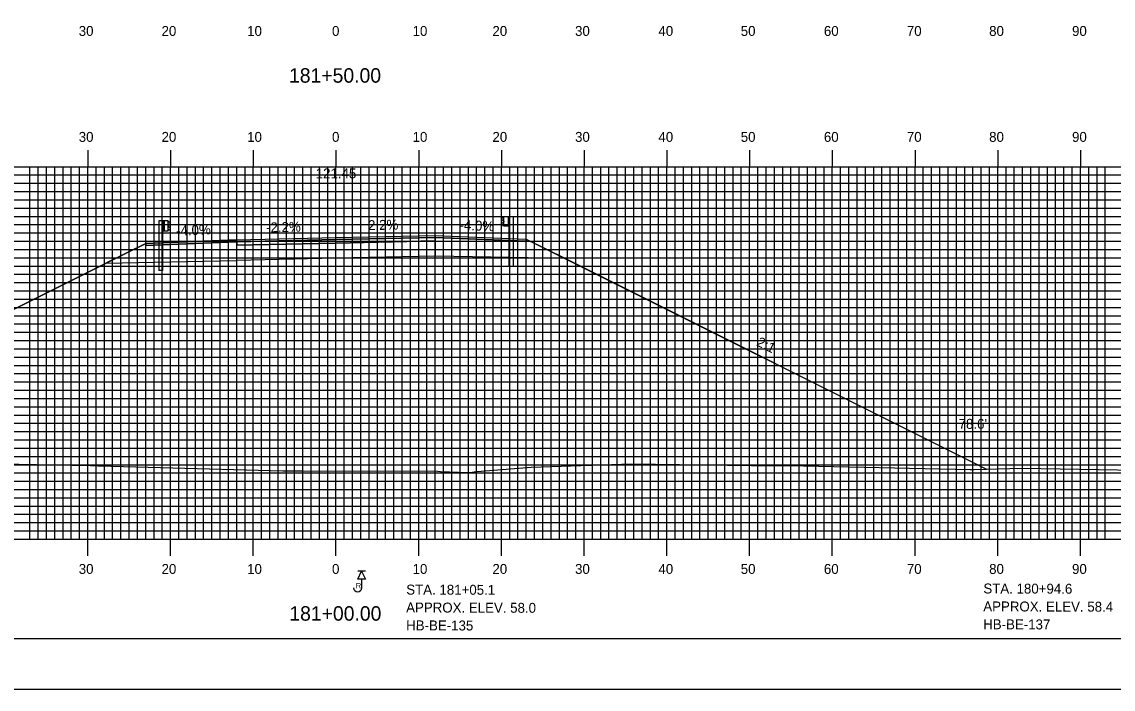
# Model space of a CAD drawing. Extents: x 1786189 to 1786532, y 442591 to 442811.
# Drawn here: x 1786316.6 to 1786448.5, y 442590.5 to 442671.2 of the extents above; entities that cross this region are included whole.
import ezdxf

# ---------------------------------------------------------------- set-up
doc = ezdxf.new("R2010")
doc.units = 0
for name, color, linetype in [('ANNOTATION', 7, 'Continuous'), ('BORDER', 7, 'Continuous'), ('BORING - NO REFUSAL', 7, 'Continuous'), ('BORING - REFUSAL', 7, 'Continuous'), ('D_Guardrail_Beam_Lt', 7, 'Continuous'), ('D_Guardrail_Beam_Rt', 7, 'Continuous'), ('D_Roadway_Centerline', 7, 'Continuous'), ('D_Roadway_Centerline_Text', 7, 'Continuous'), ('D_Roadway_Edge_Shoulder', 7, 'Continuous'), ('D_Roadway_Edge_TW', 7, 'Continuous'), ('D_Roadway_Pavement', 7, 'Continuous'), ('D_Roadway_SlopeLines', 7, 'Continuous'), ('D_Roadway_SubGrade', 7, 'Continuous'), ('D_Text_Standard', 7, 'Continuous'), ('H_V ANNOTATION', 7, 'Continuous'), ('MAJOR', 7, 'Continuous'), ('MINOR', 7, 'Continuous'), ('PLOT BOUNDARY', 7, 'Continuous'), ('S_Roadway_Centerline', 7, 'Continuous')]:
    doc.layers.add(name, color=color, linetype=linetype)

msp = doc.modelspace()

# ---------------------------------------------------------------- linework, layer by layer
at = {"layer": 'BORDER'}
msp.add_lwpolyline([(1786204.96, 442596.67), (1786524.96, 442596.67), (1786524.96, 442806.67), (1786204.96, 442806.67)], close=True, dxfattribs=at)
at = {"layer": 'BORING - NO REFUSAL'}
for p, q in [((1786358.14, 442604.81), (1786357.19, 442604.81)), ((1786357.66, 442603.85), (1786357.66, 442602.79))]:
    msp.add_line(p, q, dxfattribs=at)
msp.add_lwpolyline([(1786357.66, 442604.81), (1786358.14, 442603.85), (1786357.19, 442603.85)], close=True, dxfattribs=at)
msp.add_arc((1786357.18, 442602.79), 0.485, 180, 0, dxfattribs=at)
at = {"layer": 'D_Guardrail_Beam_Lt'}
for p, q in [((1786333.14, 442647.11), (1786333.14, 442641.11)), ((1786333.61, 442647.11), (1786333.14, 442647.11)), ((1786334.29, 442647.11), (1786333.61, 442647.11)), ((1786333.61, 442647.11), (1786333.61, 442645.94)), ((1786333.67, 442647.11), (1786333.67, 442645.94)), ((1786333.77, 442647.11), (1786333.77, 442645.94)), ((1786334.29, 442645.94), (1786334.29, 442647.11)), ((1786334.29, 442647.03), (1786334.37, 442647.01)), ((1786334.53, 442646.76), (1786334.33, 442646.63)), ((1786334.38, 442647.01), (1786334.53, 442646.91)), ((1786333.61, 442645.94), (1786334.29, 442645.94)), ((1786333.63, 442641.11), (1786333.63, 442645.94)), ((1786334.37, 442646.04), (1786334.29, 442646.03)), ((1786334.3, 442646.56), (1786334.3, 442646.49)), ((1786334.33, 442646.43), (1786334.53, 442646.29)), ((1786334.53, 442646.15), (1786334.38, 442646.05)), ((1786333.63, 442641.11), (1786333.14, 442641.11))]:
    msp.add_line(p, q, dxfattribs=at)
for centre, major_axis, start_param, end_param in [((1786334.36, 442646.97), (0.0417, 0), 0.959931, 1.376053), ((1786334.48, 442646.83), (0.0877, 0), 5.323254, 7.243116), ((1786334.38, 442646.56), (-0.0789, 0), 5.323254, 6.283185), ((1786334.38, 442646.49), (-0.0789, 0), 6.283185, 7.243116), ((1786334.36, 442646.08), (0.0417, 0), 4.907132, 5.323254), ((1786334.48, 442646.22), (0.0877, 0), 5.323254, 7.243116)]:
    msp.add_ellipse(centre, major_axis=major_axis, ratio=0.995501, start_param=start_param, end_param=end_param, dxfattribs=at)
at = {"layer": 'D_Guardrail_Beam_Rt'}
for p, q in [((1786374.75, 442647.53), (1786374.6, 442647.43)), ((1786374.6, 442647.29), (1786374.8, 442647.15)), ((1786374.8, 442646.95), (1786374.6, 442646.82)), ((1786374.84, 442647.55), (1786374.76, 442647.54)), ((1786374.83, 442647.09), (1786374.83, 442647.02)), ((1786374.84, 442647.64), (1786375.52, 442647.64)), ((1786374.84, 442646.47), (1786374.84, 442647.64)), ((1786375.36, 442647.64), (1786375.36, 442646.47)), ((1786375.46, 442647.64), (1786375.46, 442646.47)), ((1786375.52, 442647.64), (1786375.99, 442647.64)), ((1786375.52, 442647.64), (1786375.52, 442646.47)), ((1786375.99, 442647.64), (1786375.99, 442641.64)), ((1786374.6, 442646.68), (1786374.75, 442646.58)), ((1786374.76, 442646.57), (1786374.84, 442646.55)), ((1786375.52, 442646.47), (1786374.84, 442646.47)), ((1786375.5, 442641.64), (1786375.5, 442646.47)), ((1786375.5, 442641.64), (1786375.99, 442641.64))]:
    msp.add_line(p, q, dxfattribs=at)
for centre, major_axis, start_param, end_param in [((1786374.65, 442647.36), (-0.0877, 0), 5.323254, 7.243116), ((1786374.65, 442646.75), (-0.0877, 0), 5.323254, 7.243116), ((1786374.77, 442647.5), (-0.0417, 0), 4.907132, 5.323254), ((1786374.75, 442647.09), (0.0789, 0), 0, 0.959931), ((1786374.75, 442647.02), (0.0789, 0), 5.323254, 6.283185), ((1786374.77, 442646.61), (-0.0417, 0), 0.959931, 1.376053)]:
    msp.add_ellipse(centre, major_axis=major_axis, ratio=0.995501, start_param=start_param, end_param=end_param, dxfattribs=at)
at = {"layer": 'D_Roadway_Centerline'}
msp.add_lwpolyline([(1786279.32, 442618.29), (1786326.75, 442642), (1786331.56, 442644.41), (1786334.56, 442644.53), (1786342.56, 442644.85), (1786354.56, 442645.11), (1786366.56, 442645.37), (1786374.56, 442645.05), (1786377.56, 442644.93), (1786382.31, 442642.56), (1786433.18, 442617.13)], dxfattribs=at)
at = {"layer": 'D_Roadway_Edge_Shoulder'}
for points in [[(1786342.56, 442644.85), (1786334.56, 442644.53), (1786334.56, 442644.53), (1786331.56, 442644.41), (1786331.56, 442644.16), (1786342.56, 442644.6)], [(1786366.56, 442645.37), (1786374.56, 442645.05), (1786374.56, 442645.05), (1786377.56, 442644.93), (1786377.56, 442644.68), (1786366.56, 442645.12)]]:
    msp.add_lwpolyline(points, close=True, dxfattribs=at)
at = {"layer": 'D_Roadway_Edge_TW'}
msp.add_lwpolyline([(1786342.56, 442644.6), (1786342.56, 442644.85), (1786354.56, 442645.11), (1786366.56, 442645.37), (1786366.56, 442645.12), (1786354.56, 442644.86)], close=True, dxfattribs=at)
at = {"layer": 'D_Roadway_Pavement'}
msp.add_lwpolyline([(1786342.56, 442644.18), (1786342.56, 442644.6), (1786354.56, 442644.86), (1786366.56, 442645.12), (1786366.56, 442644.71), (1786354.56, 442644.44)], close=True, dxfattribs=at)
for points in [[(1786342.56, 442644.6), (1786342.56, 442644.18)], [(1786366.56, 442645.12), (1786366.56, 442644.71)]]:
    msp.add_lwpolyline(points, dxfattribs=at)
at = {"layer": 'D_Roadway_SlopeLines'}
for points in [[(1786331.56, 442644.41), (1786279.32, 442618.29)], [(1786377.56, 442644.93), (1786433.18, 442617.13)]]:
    msp.add_lwpolyline(points, dxfattribs=at)
at = {"layer": 'D_Roadway_SubGrade'}
for points in [[(1786342.56, 442644.18), (1786342.56, 442644.6), (1786331.56, 442644.16), (1786331.56, 442644.41), (1786326.75, 442642), (1786342.56, 442642.35)], [(1786342.56, 442642.35), (1786342.56, 442644.6), (1786342.56, 442644.18), (1786354.56, 442644.44), (1786366.56, 442644.71), (1786366.56, 442645.12), (1786366.56, 442642.87), (1786354.56, 442642.61)], [(1786366.56, 442644.71), (1786366.56, 442645.12), (1786377.56, 442644.68), (1786377.56, 442644.93), (1786382.31, 442642.56), (1786366.56, 442642.87)]]:
    msp.add_lwpolyline(points, close=True, dxfattribs=at)
at = {"layer": 'MAJOR'}
for p, q in [((1786324.56, 442655.67), (1786324.56, 442653.67)), ((1786334.56, 442655.67), (1786334.56, 442653.67)), ((1786344.56, 442655.67), (1786344.56, 442653.67)), ((1786354.56, 442655.67), (1786354.56, 442653.67)), ((1786364.56, 442655.67), (1786364.56, 442653.67)), ((1786374.56, 442655.67), (1786374.56, 442653.67)), ((1786384.56, 442655.67), (1786384.56, 442653.67)), ((1786394.56, 442655.67), (1786394.56, 442653.67)), ((1786404.56, 442655.67), (1786404.56, 442653.67)), ((1786414.56, 442655.67), (1786414.56, 442653.67)), ((1786424.56, 442655.67), (1786424.56, 442653.67)), ((1786434.56, 442655.67), (1786434.56, 442653.67)), ((1786444.56, 442655.67), (1786444.56, 442653.67)), ((1786214.56, 442653.67), (1786494.56, 442653.67)), ((1786214.56, 442653.67), (1786494.56, 442653.67)), ((1786324.56, 442608.67), (1786324.56, 442653.67)), ((1786334.56, 442608.67), (1786334.56, 442653.67)), ((1786344.56, 442608.67), (1786344.56, 442653.67)), ((1786354.56, 442608.67), (1786354.56, 442653.67)), ((1786364.56, 442608.67), (1786364.56, 442653.67)), ((1786374.56, 442608.67), (1786374.56, 442653.67)), ((1786384.56, 442608.67), (1786384.56, 442653.67)), ((1786394.56, 442608.67), (1786394.56, 442653.67)), ((1786404.56, 442608.67), (1786404.56, 442653.67)), ((1786414.56, 442608.67), (1786414.56, 442653.67)), ((1786424.56, 442608.67), (1786424.56, 442653.67)), ((1786434.56, 442608.67), (1786434.56, 442653.67)), ((1786444.56, 442608.67), (1786444.56, 442653.67)), ((1786214.56, 442648.67), (1786494.56, 442648.67)), ((1786214.56, 442643.67), (1786494.56, 442643.67)), ((1786214.56, 442638.67), (1786494.56, 442638.67)), ((1786214.56, 442633.67), (1786494.56, 442633.67)), ((1786214.56, 442628.67), (1786494.56, 442628.67)), ((1786214.56, 442623.67), (1786494.56, 442623.67)), ((1786214.56, 442618.67), (1786494.56, 442618.67)), ((1786214.56, 442613.67), (1786494.56, 442613.67)), ((1786214.56, 442608.67), (1786494.56, 442608.67)), ((1786214.56, 442608.67), (1786494.56, 442608.67)), ((1786324.56, 442606.66), (1786324.56, 442608.67)), ((1786334.56, 442606.66), (1786334.56, 442608.67)), ((1786344.56, 442606.66), (1786344.56, 442608.67)), ((1786354.56, 442606.66), (1786354.56, 442608.67)), ((1786364.56, 442606.66), (1786364.56, 442608.67)), ((1786374.56, 442606.66), (1786374.56, 442608.67)), ((1786384.56, 442606.66), (1786384.56, 442608.67)), ((1786394.56, 442606.66), (1786394.56, 442608.67)), ((1786404.56, 442606.66), (1786404.56, 442608.67)), ((1786414.56, 442606.66), (1786414.56, 442608.67)), ((1786424.56, 442606.66), (1786424.56, 442608.67)), ((1786434.56, 442606.66), (1786434.56, 442608.67)), ((1786444.56, 442606.66), (1786444.56, 442608.67))]:
    msp.add_line(p, q, dxfattribs=at)
at = {"layer": 'MINOR'}
for p, q in [((1786317.56, 442608.67), (1786317.56, 442653.67)), ((1786318.56, 442608.67), (1786318.56, 442653.67)), ((1786319.56, 442608.67), (1786319.56, 442653.67)), ((1786320.56, 442608.67), (1786320.56, 442653.67)), ((1786321.56, 442608.67), (1786321.56, 442653.67)), ((1786322.56, 442608.67), (1786322.56, 442653.67)), ((1786323.56, 442608.67), (1786323.56, 442653.67)), ((1786325.56, 442608.67), (1786325.56, 442653.67)), ((1786326.56, 442608.67), (1786326.56, 442653.67)), ((1786327.56, 442608.67), (1786327.56, 442653.67)), ((1786328.56, 442608.67), (1786328.56, 442653.67)), ((1786329.56, 442608.67), (1786329.56, 442653.67)), ((1786330.56, 442608.67), (1786330.56, 442653.67)), ((1786331.56, 442608.67), (1786331.56, 442653.67)), ((1786332.56, 442608.67), (1786332.56, 442653.67)), ((1786333.56, 442608.67), (1786333.56, 442653.67)), ((1786335.56, 442608.67), (1786335.56, 442653.67)), ((1786336.56, 442608.67), (1786336.56, 442653.67)), ((1786337.56, 442608.67), (1786337.56, 442653.67)), ((1786338.56, 442608.67), (1786338.56, 442653.67)), ((1786339.56, 442608.67), (1786339.56, 442653.67)), ((1786340.56, 442608.67), (1786340.56, 442653.67)), ((1786341.56, 442608.67), (1786341.56, 442653.67)), ((1786342.56, 442608.67), (1786342.56, 442653.67)), ((1786343.56, 442608.67), (1786343.56, 442653.67)), ((1786345.56, 442608.67), (1786345.56, 442653.67)), ((1786346.56, 442608.67), (1786346.56, 442653.67)), ((1786347.56, 442608.67), (1786347.56, 442653.67)), ((1786348.56, 442608.67), (1786348.56, 442653.67)), ((1786349.56, 442608.67), (1786349.56, 442653.67)), ((1786350.56, 442608.67), (1786350.56, 442653.67)), ((1786351.56, 442608.67), (1786351.56, 442653.67)), ((1786352.56, 442608.67), (1786352.56, 442653.67)), ((1786353.56, 442608.67), (1786353.56, 442653.67)), ((1786355.56, 442608.67), (1786355.56, 442653.67)), ((1786356.56, 442608.67), (1786356.56, 442653.67)), ((1786357.56, 442608.67), (1786357.56, 442653.67)), ((1786358.56, 442608.67), (1786358.56, 442653.67)), ((1786359.56, 442608.67), (1786359.56, 442653.67)), ((1786360.56, 442608.67), (1786360.56, 442653.67)), ((1786361.56, 442608.67), (1786361.56, 442653.67)), ((1786362.56, 442608.67), (1786362.56, 442653.67)), ((1786363.56, 442608.67), (1786363.56, 442653.67)), ((1786365.56, 442608.67), (1786365.56, 442653.67)), ((1786366.56, 442608.67), (1786366.56, 442653.67)), ((1786367.56, 442608.67), (1786367.56, 442653.67)), ((1786368.56, 442608.67), (1786368.56, 442653.67)), ((1786369.56, 442608.67), (1786369.56, 442653.67)), ((1786370.56, 442608.67), (1786370.56, 442653.67)), ((1786371.56, 442608.67), (1786371.56, 442653.67)), ((1786372.56, 442608.67), (1786372.56, 442653.67)), ((1786373.56, 442608.67), (1786373.56, 442653.67)), ((1786375.56, 442608.67), (1786375.56, 442653.67)), ((1786376.56, 442608.67), (1786376.56, 442653.67)), ((1786377.56, 442608.67), (1786377.56, 442653.67)), ((1786378.56, 442608.67), (1786378.56, 442653.67)), ((1786379.56, 442608.67), (1786379.56, 442653.67)), ((1786380.56, 442608.67), (1786380.56, 442653.67)), ((1786381.56, 442608.67), (1786381.56, 442653.67)), ((1786382.56, 442608.67), (1786382.56, 442653.67)), ((1786383.56, 442608.67), (1786383.56, 442653.67)), ((1786385.56, 442608.67), (1786385.56, 442653.67)), ((1786386.56, 442608.67), (1786386.56, 442653.67)), ((1786387.56, 442608.67), (1786387.56, 442653.67)), ((1786388.56, 442608.67), (1786388.56, 442653.67)), ((1786389.56, 442608.67), (1786389.56, 442653.67)), ((1786390.56, 442608.67), (1786390.56, 442653.67)), ((1786391.56, 442608.67), (1786391.56, 442653.67)), ((1786392.56, 442608.67), (1786392.56, 442653.67)), ((1786393.56, 442608.67), (1786393.56, 442653.67)), ((1786395.56, 442608.67), (1786395.56, 442653.67)), ((1786396.56, 442608.67), (1786396.56, 442653.67)), ((1786397.56, 442608.67), (1786397.56, 442653.67)), ((1786398.56, 442608.67), (1786398.56, 442653.67)), ((1786399.56, 442608.67), (1786399.56, 442653.67)), ((1786400.56, 442608.67), (1786400.56, 442653.67)), ((1786401.56, 442608.67), (1786401.56, 442653.67)), ((1786402.56, 442608.67), (1786402.56, 442653.67)), ((1786403.56, 442608.67), (1786403.56, 442653.67)), ((1786405.56, 442608.67), (1786405.56, 442653.67)), ((1786406.56, 442608.67), (1786406.56, 442653.67)), ((1786407.56, 442608.67), (1786407.56, 442653.67)), ((1786408.56, 442608.67), (1786408.56, 442653.67)), ((1786409.56, 442608.67), (1786409.56, 442653.67)), ((1786410.56, 442608.67), (1786410.56, 442653.67)), ((1786411.56, 442608.67), (1786411.56, 442653.67)), ((1786412.56, 442608.67), (1786412.56, 442653.67)), ((1786413.56, 442608.67), (1786413.56, 442653.67)), ((1786415.56, 442608.67), (1786415.56, 442653.67)), ((1786416.56, 442608.67), (1786416.56, 442653.67)), ((1786417.56, 442608.67), (1786417.56, 442653.67)), ((1786418.56, 442608.67), (1786418.56, 442653.67)), ((1786419.56, 442608.67), (1786419.56, 442653.67)), ((1786420.56, 442608.67), (1786420.56, 442653.67)), ((1786421.56, 442608.67), (1786421.56, 442653.67)), ((1786422.56, 442608.67), (1786422.56, 442653.67)), ((1786423.56, 442608.67), (1786423.56, 442653.67)), ((1786425.56, 442608.67), (1786425.56, 442653.67)), ((1786426.56, 442608.67), (1786426.56, 442653.67)), ((1786427.56, 442608.67), (1786427.56, 442653.67)), ((1786428.56, 442608.67), (1786428.56, 442653.67)), ((1786429.56, 442608.67), (1786429.56, 442653.67)), ((1786430.56, 442608.67), (1786430.56, 442653.67)), ((1786431.56, 442608.67), (1786431.56, 442653.67)), ((1786432.56, 442608.67), (1786432.56, 442653.67)), ((1786433.56, 442608.67), (1786433.56, 442653.67)), ((1786435.56, 442608.67), (1786435.56, 442653.67)), ((1786436.56, 442608.67), (1786436.56, 442653.67)), ((1786437.56, 442608.67), (1786437.56, 442653.67)), ((1786438.56, 442608.67), (1786438.56, 442653.67)), ((1786439.56, 442608.67), (1786439.56, 442653.67)), ((1786440.56, 442608.67), (1786440.56, 442653.67)), ((1786441.56, 442608.67), (1786441.56, 442653.67)), ((1786442.56, 442608.67), (1786442.56, 442653.67)), ((1786443.56, 442608.67), (1786443.56, 442653.67)), ((1786445.56, 442608.67), (1786445.56, 442653.67)), ((1786446.56, 442608.67), (1786446.56, 442653.67)), ((1786447.56, 442608.67), (1786447.56, 442653.67)), ((1786214.56, 442652.67), (1786494.56, 442652.67)), ((1786214.56, 442651.67), (1786494.56, 442651.67)), ((1786214.56, 442650.67), (1786494.56, 442650.67)), ((1786214.56, 442649.67), (1786494.56, 442649.67)), ((1786214.56, 442647.67), (1786494.56, 442647.67)), ((1786214.56, 442646.67), (1786494.56, 442646.67)), ((1786214.56, 442645.67), (1786494.56, 442645.67)), ((1786214.56, 442644.67), (1786494.56, 442644.67)), ((1786214.56, 442642.67), (1786494.56, 442642.67)), ((1786214.56, 442641.67), (1786494.56, 442641.67)), ((1786214.56, 442640.67), (1786494.56, 442640.67)), ((1786214.56, 442639.67), (1786494.56, 442639.67)), ((1786214.56, 442637.67), (1786494.56, 442637.67)), ((1786214.56, 442636.67), (1786494.56, 442636.67)), ((1786214.56, 442635.67), (1786494.56, 442635.67)), ((1786214.56, 442634.67), (1786494.56, 442634.67)), ((1786214.56, 442632.67), (1786494.56, 442632.67)), ((1786214.56, 442631.67), (1786494.56, 442631.67)), ((1786214.56, 442630.67), (1786494.56, 442630.67)), ((1786214.56, 442629.67), (1786494.56, 442629.67)), ((1786214.56, 442627.67), (1786494.56, 442627.67)), ((1786214.56, 442626.67), (1786494.56, 442626.67)), ((1786214.56, 442625.67), (1786494.56, 442625.67)), ((1786214.56, 442624.67), (1786494.56, 442624.67)), ((1786214.56, 442622.67), (1786494.56, 442622.67)), ((1786214.56, 442621.67), (1786494.56, 442621.67)), ((1786214.56, 442620.67), (1786494.56, 442620.67)), ((1786214.56, 442619.67), (1786494.56, 442619.67)), ((1786214.56, 442617.67), (1786494.56, 442617.67)), ((1786214.56, 442616.67), (1786494.56, 442616.67)), ((1786214.56, 442615.67), (1786494.56, 442615.67)), ((1786214.56, 442614.67), (1786494.56, 442614.67)), ((1786214.56, 442612.67), (1786494.56, 442612.67)), ((1786214.56, 442611.67), (1786494.56, 442611.67)), ((1786214.56, 442610.67), (1786494.56, 442610.67)), ((1786214.56, 442609.67), (1786494.56, 442609.67))]:
    msp.add_line(p, q, dxfattribs=at)
at = {"layer": 'PLOT BOUNDARY'}
msp.add_lwpolyline([(1786188.78, 442590.55), (1786528.78, 442590.55), (1786528.78, 442810.55), (1786188.78, 442810.55)], close=True, dxfattribs=at)
at = {"layer": 'S_Roadway_Centerline'}
msp.add_lwpolyline([(1786314.04, 442617.77), (1786324.86, 442617.57), (1786325.3, 442617.55), (1786325.33, 442617.55), (1786325.36, 442617.55), (1786325.45, 442617.55), (1786325.48, 442617.55), (1786325.51, 442617.55), (1786325.54, 442617.55), (1786325.57, 442617.55), (1786325.6, 442617.55), (1786325.64, 442617.55), (1786325.67, 442617.55), (1786325.69, 442617.55), (1786325.72, 442617.55), (1786325.74, 442617.55), (1786325.76, 442617.55), (1786325.77, 442617.55), (1786325.78, 442617.54), (1786325.82, 442617.54), (1786325.84, 442617.54), (1786325.85, 442617.54), (1786325.87, 442617.54), (1786325.88, 442617.54), (1786333.36, 442617.33), (1786348.14, 442616.94), (1786350.55, 442616.92), (1786366.87, 442616.87), (1786367.2, 442616.85), (1786367.86, 442616.82), (1786368.28, 442616.8), (1786368.78, 442616.78), (1786369.37, 442616.75), (1786370.07, 442616.73), (1786370.61, 442616.71), (1786370.72, 442616.72), (1786371.03, 442616.77), (1786371.27, 442616.81), (1786371.47, 442616.84), (1786371.64, 442616.86), (1786378.16, 442617.36), (1786390.29, 442617.76), (1786404.8, 442617.56), (1786409.27, 442617.56), (1786431.22, 442617.09), (1786431.67, 442617.07), (1786433.16, 442617.13), (1786437.49, 442617.23), (1786451.36, 442617)], dxfattribs=at)

# ---------------------------------------------------------------- texts
at = {"layer": 'ANNOTATION'}
for s, rotation, p in [('-2.2%', 1.2603, (1786346.12, 442645.73)), ('2.2%', 1.2603, (1786358.45, 442646)), ('-4.0%', 357.7094, (1786369.47, 442646.04)), ('-4.0%', 2.2906, (1786335.25, 442645.33)), ('2:1', 333.4349, (1786405.3, 442632.1))]:
    msp.add_text(s, height=1.2, rotation=rotation, dxfattribs=at).set_placement(p)
at = {"layer": 'BORING - NO REFUSAL'}
msp.add_text('R', height=0.64, dxfattribs=at).set_placement((1786356.96, 442602.73))
at = {"layer": 'BORING - REFUSAL'}
for s, p in [('STA. 181+05.1', (1786363.05, 442601.98)), ('STA. 180+94.6', (1786432.82, 442602.11)), ('APPROX. ELEV. 58.0', (1786363.04, 442599.82)), ('APPROX. ELEV. 58.4', (1786432.81, 442599.95)), ('HB-BE-135', (1786363.04, 442597.66)), ('HB-BE-137', (1786432.8, 442597.79))]:
    msp.add_text(s, height=1.2, rotation=359.8142, dxfattribs=at).set_placement(p)
at = {"layer": 'D_Roadway_Centerline'}
for s, p in [('C', (1786354.56, 442645.11)), ('L', (1786354.56, 442645.1))]:
    msp.add_text(s, height=0.0146, dxfattribs=at).set_placement(p)
at = {"layer": 'D_Roadway_Centerline_Text'}
msp.add_text('121.45', height=1.2, dxfattribs=at).set_placement((1786352.11, 442652.26))
at = {"layer": 'D_Text_Standard'}
msp.add_text("78.6'", height=1.2, dxfattribs=at).set_placement((1786429.83, 442622))
at = {"layer": 'H_V ANNOTATION'}
for s, height, p in [('30', 1.2, (1786323.46, 442669.47)), ('20', 1.2, (1786333.47, 442669.47)), ('10', 1.2, (1786343.82, 442669.47)), ('0', 1.2, (1786354.08, 442669.47)), ('10', 1.2, (1786363.82, 442669.47)), ('20', 1.2, (1786373.47, 442669.47)), ('30', 1.2, (1786383.46, 442669.47)), ('40', 1.2, (1786393.54, 442669.47)), ('50', 1.2, (1786403.49, 442669.47)), ('60', 1.2, (1786413.54, 442669.47)), ('70', 1.2, (1786423.57, 442669.47)), ('80', 1.2, (1786433.52, 442669.47)), ('90', 1.2, (1786443.54, 442669.47)), ('181+50.00', 1.75, (1786348.88, 442663.82)), ('30', 1.2, (1786323.46, 442656.67)), ('20', 1.2, (1786333.47, 442656.67)), ('10', 1.2, (1786343.82, 442656.67)), ('0', 1.2, (1786354.08, 442656.67)), ('10', 1.2, (1786363.82, 442656.67)), ('20', 1.2, (1786373.47, 442656.67)), ('30', 1.2, (1786383.46, 442656.67)), ('40', 1.2, (1786393.54, 442656.67)), ('50', 1.2, (1786403.49, 442656.67)), ('60', 1.2, (1786413.54, 442656.67)), ('70', 1.2, (1786423.57, 442656.67)), ('80', 1.2, (1786433.52, 442656.67)), ('90', 1.2, (1786443.54, 442656.67)), ('30', 1.2, (1786323.46, 442604.47)), ('20', 1.2, (1786333.47, 442604.47)), ('10', 1.2, (1786343.82, 442604.47)), ('0', 1.2, (1786354.08, 442604.47)), ('10', 1.2, (1786363.82, 442604.47)), ('20', 1.2, (1786373.47, 442604.47)), ('30', 1.2, (1786383.46, 442604.47)), ('40', 1.2, (1786393.54, 442604.47)), ('50', 1.2, (1786403.49, 442604.47)), ('60', 1.2, (1786413.54, 442604.47)), ('70', 1.2, (1786423.57, 442604.47)), ('80', 1.2, (1786433.52, 442604.47)), ('90', 1.2, (1786443.54, 442604.47)), ('181+00.00', 1.75, (1786348.92, 442598.82))]:
    msp.add_text(s, height=height, dxfattribs=at).set_placement(p)

doc.saveas('drawing.dxf')
